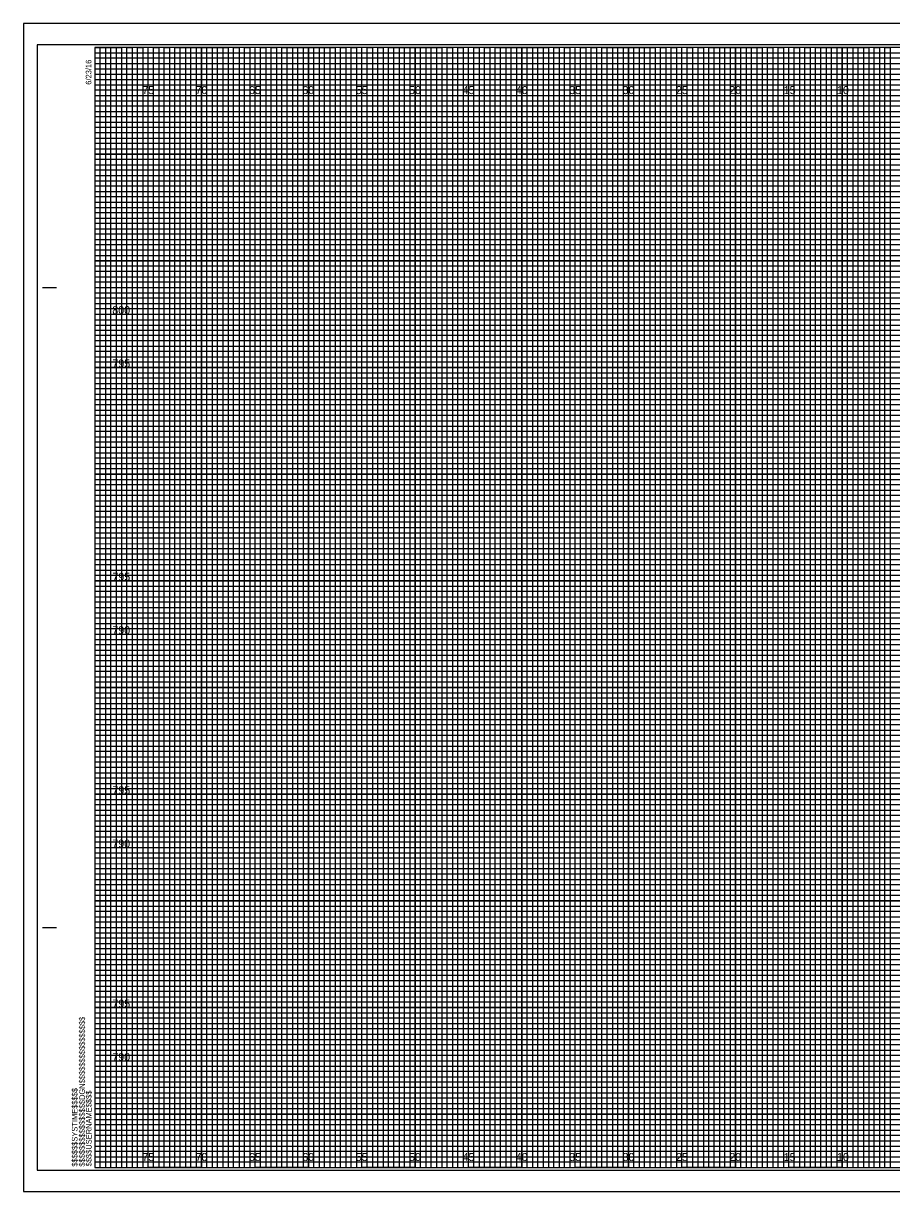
# Model space of a CAD drawing. Extents: x -7 to 162, y -2 to 107.
# Drawn here: x -6.7 to 74.6, y -2.3 to 107.3 of the extents above; entities that cross this region are included whole.
import ezdxf

# ---------------------------------------------------------------- set-up
doc = ezdxf.new("R2010")
doc.units = 0
for name, color, linetype in [('Exist CMT Pavement', 7, 'Continuous'), ('Exist Cross Section Cell', 7, 'Continuous'), ('Exist XS Center Line Elevation Label', 7, 'Continuous'), ('Prop CMT Concrete Structures', 7, 'Continuous'), ('Prop CMT Pvmt Course 1 Wedge', 7, 'Continuous'), ('Prop CMT Pvmt Course 2', 7, 'Continuous'), ('Prop CMT Pvmt Course 2 Wedge', 7, 'Continuous'), ('Prop CMT Pvmt Course 3', 7, 'Continuous'), ('Prop XS Offset Labels', 7, 'Continuous'), ('Scratch_Level_0', 7, 'Continuous'), ('Sheet DOT Grid CELL', 7, 'Continuous')]:
    doc.layers.add(name, color=color, linetype=linetype)

msp = doc.modelspace()

# ---------------------------------------------------------------- linework, layer by layer
at = {"layer": 'Exist Cross Section Cell'}
for p, q in [((5, 105), (0, 105)), ((5, 0), (5, 105)), ((15, 105), (10, 105)), ((10, 105), (10, 0)), ((15, 0), (15, 105)), ((25, 105), (20, 105)), ((20, 105), (20, 0)), ((25, 0), (25, 105)), ((35, 105), (30, 105)), ((30, 105), (30, 0)), ((35, 0), (35, 105)), ((45, 105), (40, 105)), ((40, 105), (40, 0)), ((45, 0), (45, 105)), ((55, 105), (50, 105)), ((50, 105), (50, 0)), ((55, 0), (55, 105)), ((65, 105), (60, 105)), ((60, 105), (60, 0)), ((65, 0), (65, 105)), ((75, 105), (70, 105)), ((70, 105), (70, 0)), ((10, 0), (5, 0)), ((20, 0), (15, 0)), ((30, 0), (25, 0)), ((40, 0), (35, 0)), ((50, 0), (45, 0)), ((60, 0), (55, 0)), ((70, 0), (65, 0))]:
    msp.add_line(p, q, dxfattribs=at)
for points in [[(0, 100), (160, 100), (160, 95), (0, 95)], [(0, 90), (160, 90), (160, 85), (0, 85)], [(0, 80), (160, 80), (160, 75), (0, 75)], [(0, 70), (160, 70), (160, 65), (0, 65)], [(0, 60), (160, 60), (160, 55), (0, 55)], [(0, 50), (160, 50), (160, 45), (0, 45)], [(0, 40), (160, 40), (160, 35), (0, 35)], [(0, 30), (160, 30), (160, 25), (0, 25)], [(0, 20), (160, 20), (160, 15), (0, 15)], [(0, 10), (160, 10), (160, 5), (0, 5)]]:
    msp.add_lwpolyline(points, dxfattribs=at)
at = {"layer": 'Exist XS Center Line Elevation Label'}
for points in [[(0, 105), (2.5, 105), (2.5, 0), (7.5, 0), (7.5, 105), (12.5, 105), (12.5, 0), (17.5, 0), (17.5, 105), (22.5, 105), (22.5, 0), (27.5, 0), (27.5, 105), (32.5, 105), (32.5, 0), (37.5, 0), (37.5, 105), (42.5, 105), (42.5, 0), (47.5, 0), (47.5, 105), (52.5, 105), (52.5, 0), (57.5, 0), (57.5, 105), (62.5, 105), (62.5, 0), (67.5, 0), (67.5, 105), (72.5, 105), (72.5, 0), (77.5, 0)], [(0, 102.5), (137.5, 102.5)], [(0, 92.5), (160, 92.5), (160, 97.5), (0, 97.5)], [(0, 82.5), (160, 82.5), (160, 87.5), (0, 87.5)], [(0, 72.5), (160, 72.5), (160, 77.5), (0, 77.5)], [(0, 62.5), (160, 62.5), (160, 67.5), (0, 67.5)], [(0, 52.5), (160, 52.5), (160, 57.5), (0, 57.5)], [(0, 42.5), (160, 42.5), (160, 47.5), (0, 47.5)], [(0, 32.5), (160, 32.5), (160, 37.5), (0, 37.5)], [(0, 22.5), (160, 22.5), (160, 27.5), (0, 27.5)], [(0, 12.5), (160, 12.5), (160, 17.5), (0, 17.5)], [(0, 2.5), (160, 2.5), (160, 7.5), (0, 7.5)]]:
    msp.add_lwpolyline(points, dxfattribs=at)
at = {"layer": 'Prop CMT Concrete Structures'}
for p, q in [((161.65, 107.25), (-6.7, 107.25)), ((-6.7, 107.25), (-6.7, -2.25)), ((-6.7, -2.25), (161.65, -2.25))]:
    msp.add_line(p, q, dxfattribs=at)
at = {"layer": 'Prop CMT Pvmt Course 1 Wedge'}
msp.add_lwpolyline([(-6.7, -2.25), (161.65, -2.25), (161.65, 107.25), (-6.7, 107.25)], close=True, dxfattribs=at)
at = {"layer": 'Prop CMT Pvmt Course 2'}
for p, q in [((-4.9, 82.5), (-3.65, 82.5)), ((-4.85, 82.5), (-3.6, 82.5)), ((-4.9, 22.5), (-3.65, 22.5)), ((-4.85, 22.5), (-3.6, 22.5)), ((0, 0), (0, 0)), ((0, 0), (0, 0)), ((0, 0), (0, 0)), ((0, 0), (0, 0)), ((0, 0), (0, 0)), ((0, 0), (0, 0)), ((0, 0), (0, 0))]:
    msp.add_line(p, q, dxfattribs=at)
msp.add_lwpolyline([(160, 105), (0, 105), (0, 0), (160, 0)], close=True, dxfattribs=at)
at = {"layer": 'Prop CMT Pvmt Course 2 Wedge'}
msp.add_lwpolyline([(-5.4, -0.25), (161.2, -0.25), (161.2, 105.25), (-5.4, 105.25)], close=True, dxfattribs=at)
at = {"layer": 'Prop CMT Pvmt Course 3'}
for points in [[(0, 0), (0.5, 0), (0.5, 105), (1, 105), (1, 0)], [(1, 0), (1.5, 0), (1.5, 105), (2, 105), (2, 0)], [(2.5, 0), (3, 0), (3, 105), (3.5, 105), (3.5, 0)], [(3.5, 0), (4, 0), (4, 105), (4.5, 105), (4.5, 0)], [(5, 0), (5.5, 0), (5.5, 105), (6, 105), (6, 0)], [(6, 0), (6.5, 0), (6.5, 105), (7, 105), (7, 0)], [(7.5, 0), (8, 0), (8, 105), (8.5, 105), (8.5, 0)], [(8.5, 0), (9, 0), (9, 105), (9.5, 105), (9.5, 0)], [(10, 0), (10.5, 0), (10.5, 105), (11, 105), (11, 0)], [(11, 0), (11.5, 0), (11.5, 105), (12, 105), (12, 0)], [(12.5, 0), (13, 0), (13, 105), (13.5, 105), (13.5, 0)], [(13.5, 0), (14, 0), (14, 105), (14.5, 105), (14.5, 0)], [(15, 0), (15.5, 0), (15.5, 105), (16, 105), (16, 0)], [(16, 0), (16.5, 0), (16.5, 105), (17, 105), (17, 0)], [(17.5, 0), (18, 0), (18, 105), (18.5, 105), (18.5, 0)], [(18.5, 0), (19, 0), (19, 105), (19.5, 105), (19.5, 0)], [(20, 0), (20.5, 0), (20.5, 105), (21, 105), (21, 0)], [(21, 0), (21.5, 0), (21.5, 105), (22, 105), (22, 0)], [(22.5, 0), (23, 0), (23, 105), (23.5, 105), (23.5, 0)], [(23.5, 0), (24, 0), (24, 105), (24.5, 105), (24.5, 0)], [(25, 0), (25.5, 0), (25.5, 105), (26, 105), (26, 0)], [(26, 0), (26.5, 0), (26.5, 105), (27, 105), (27, 0)], [(27.5, 0), (28, 0), (28, 105), (28.5, 105), (28.5, 0)], [(28.5, 0), (29, 0), (29, 105), (29.5, 105), (29.5, 0)], [(30, 0), (30.5, 0), (30.5, 105), (31, 105), (31, 0)], [(31, 0), (31.5, 0), (31.5, 105), (32, 105), (32, 0)], [(32.5, 0), (33, 0), (33, 105), (33.5, 105), (33.5, 0)], [(33.5, 0), (34, 0), (34, 105), (34.5, 105), (34.5, 0)], [(35, 0), (35.5, 0), (35.5, 105), (36, 105), (36, 0)], [(36, 0), (36.5, 0), (36.5, 105), (37, 105), (37, 0)], [(37.5, 0), (38, 0), (38, 105), (38.5, 105), (38.5, 0)], [(38.5, 0), (39, 0), (39, 105), (39.5, 105), (39.5, 0)], [(40, 0), (40.5, 0), (40.5, 105), (41, 105), (41, 0)], [(41, 0), (41.5, 0), (41.5, 105), (42, 105), (42, 0)], [(42.5, 0), (43, 0), (43, 105), (43.5, 105), (43.5, 0)], [(43.5, 0), (44, 0), (44, 105), (44.5, 105), (44.5, 0)], [(45, 0), (45.5, 0), (45.5, 105), (46, 105), (46, 0)], [(46, 0), (46.5, 0), (46.5, 105), (47, 105), (47, 0)], [(47.5, 0), (48, 0), (48, 105), (48.5, 105), (48.5, 0)], [(48.5, 0), (49, 0), (49, 105), (49.5, 105), (49.5, 0)], [(50, 0), (50.5, 0), (50.5, 105), (51, 105), (51, 0)], [(51, 0), (51.5, 0), (51.5, 105), (52, 105), (52, 0)], [(52.5, 0), (53, 0), (53, 105), (53.5, 105), (53.5, 0)], [(53.5, 0), (54, 0), (54, 105), (54.5, 105), (54.5, 0)], [(55, 0), (55.5, 0), (55.5, 105), (56, 105), (56, 0)], [(56, 0), (56.5, 0), (56.5, 105), (57, 105), (57, 0)], [(57.5, 0), (58, 0), (58, 105), (58.5, 105), (58.5, 0)], [(58.5, 0), (59, 0), (59, 105), (59.5, 105), (59.5, 0)], [(60, 0), (60.5, 0), (60.5, 105), (61, 105), (61, 0)], [(61, 0), (61.5, 0), (61.5, 105), (62, 105), (62, 0)], [(62.5, 0), (63, 0), (63, 105), (63.5, 105), (63.5, 0)], [(63.5, 0), (64, 0), (64, 105), (64.5, 105), (64.5, 0)], [(65, 0), (65.5, 0), (65.5, 105), (66, 105), (66, 0)], [(66, 0), (66.5, 0), (66.5, 105), (67, 105), (67, 0)], [(67.5, 0), (68, 0), (68, 105), (68.5, 105), (68.5, 0)], [(68.5, 0), (69, 0), (69, 105), (69.5, 105), (69.5, 0)], [(70, 0), (70.5, 0), (70.5, 105), (71, 105), (71, 0)], [(71, 0), (71.5, 0), (71.5, 105), (72, 105), (72, 0)], [(72.5, 0), (73, 0), (73, 105), (73.5, 105), (73.5, 0)], [(73.5, 0), (74, 0), (74, 105), (74.5, 105), (74.5, 0)]]:
    msp.add_lwpolyline(points, dxfattribs=at)
at = {"layer": 'Scratch_Level_0'}
for p, q in [((0, 104.5), (130, 104.5)), ((130, 103.99), (0, 103.99)), ((0, 103.99), (0, 103.5)), ((0, 103.5), (130, 103.5)), ((130, 102.95), (0, 102.95)), ((0, 102.95), (0, 102)), ((0, 102), (160, 102))]:
    msp.add_line(p, q, dxfattribs=at)
for points in [[(0, 101.5), (135, 101.5), (160, 101.5), (160, 101), (0, 101)], [(0, 100.5), (160, 100.5), (160, 99.5), (0, 99.5)], [(0, 99), (160, 99), (160, 98.5), (0, 98.49)], [(0, 98), (160, 98), (160, 97), (0, 97)], [(0, 96.5), (160, 96.5), (160, 96), (0, 96)], [(0, 95.5), (160, 95.5), (160, 94.5), (0, 94.5)], [(0, 94), (160, 94), (160, 93.5), (0, 93.5)], [(0, 93), (160, 93), (160, 92), (0, 92)], [(0, 91.5), (160, 91.5), (160, 91), (0, 91)], [(0, 90.5), (160, 90.5), (160, 89.5), (0, 89.5)], [(0, 89), (160, 89), (160, 88.5), (0, 88.5)], [(0, 88), (160, 88), (160, 86.98), (160, 86.5), (160, 86), (0, 86)], [(0, 87), (160, 87), (160, 86.5), (0, 86.5)], [(0, 85.5), (160, 85.5), (160, 84.5), (0, 84.52)], [(0, 84.52), (160, 84.5), (160, 84), (0, 84)], [(0, 83.5), (160, 83.5), (160, 83), (0, 83)], [(0, 82), (160, 82), (160, 81.5), (0, 81.5)], [(0, 81), (160, 81), (160, 80.5), (0, 80.5)], [(-0.04, 79.45), (160, 79.45), (160, 78.94), (-0.04, 78.94)], [(0, 78.5), (160, 78.5), (160, 78), (0, 78)], [(0, 77), (160, 77), (160, 76.5), (0, 76.5)], [(0, 76), (160, 76), (160, 75.5), (0, 75.5)], [(0, 74.5), (160, 74.5), (160, 74), (0, 74)], [(0, 73.5), (160, 73.5), (160, 73), (0, 73)], [(0, 72), (160, 72), (160, 71.5), (0, 71.5)], [(0, 71), (160, 71), (160, 70.5), (0, 70.5)], [(0, 69.5), (160, 69.5), (160, 68.99), (0, 69)], [(0, 68.5), (160, 68.5), (160, 68), (0, 68)], [(0, 67), (160, 67), (160, 66.5), (0, 66.5)], [(0, 66), (160, 66), (160, 65.5), (0, 65.5)], [(0, 64.5), (160, 64.5), (160, 64), (0, 64)], [(0, 63.5), (160, 63.5), (160, 63), (0, 63)], [(0, 62), (160, 62), (160, 61.5), (0, 61.5)], [(0, 61), (160, 61), (160, 60.5), (0, 60.5)], [(0, 59.5), (160, 59.5), (160, 59), (0, 59)], [(0, 58.5), (160.03, 58.45), (160, 58), (0, 58)], [(0, 57), (160, 57), (160, 56.5), (0, 56.5)], [(0, 56), (160, 56), (160, 55.5), (0, 55.5)], [(0, 54.5), (160, 54.5), (160, 54), (0, 54)], [(0, 53.5), (160, 53.5), (160, 53), (0, 53)], [(0, 52), (160, 52), (160, 51.5), (0, 51.5)], [(0, 51), (160, 51), (160, 50.5), (0, 50.5)], [(0, 49.5), (160, 49.5), (160, 49), (0, 49)], [(0, 48.5), (160, 48.5), (160, 48), (0, 48)], [(0, 47), (160, 47), (160, 46.5), (0, 46.5)], [(0, 46), (160, 46), (160, 45.5), (0, 45.5)], [(0, 44.5), (160, 44.5), (160, 44), (0, 44)], [(0, 43.5), (160, 43.5), (160, 43), (0, 43)], [(0, 42), (160, 42), (160, 41.5), (0, 41.5)], [(0, 41), (160, 41), (160, 40.5), (0, 40.5)], [(0, 39.5), (160, 39.5), (160, 38.99), (0, 39)], [(0, 38.5), (160, 38.5), (160, 38), (0, 38)], [(0, 37), (160, 37), (160, 36.5), (0, 36.5)], [(0, 36), (160, 36), (160, 35.5), (0, 35.5)], [(0, 34.5), (160, 34.5), (160, 34), (0, 34)], [(0, 33.5), (160, 33.5), (160, 33), (0, 33)], [(0, 32), (160, 32), (160, 31.5), (0, 31.5)], [(0, 31), (160, 31), (160, 30.5), (0, 30.5)], [(0, 29.5), (160, 29.5), (160, 29), (0, 29)], [(0, 28.5), (160.03, 28.46), (160, 28), (0, 28)], [(0, 27), (160, 27), (160, 26.5), (0, 26.5)], [(0, 26), (160, 26), (160, 25.5), (0, 25.5)], [(0, 24.5), (160, 24.5), (160, 24), (0, 24)], [(0, 23.5), (160, 23.5), (160, 23), (0, 23)], [(0, 22), (160, 22), (160, 21.5), (0, 21.5)], [(0, 21), (160, 21), (160, 20.5), (0, 20.5)], [(0, 19.5), (160, 19.5), (160, 19), (0, 19)], [(0, 18.5), (160, 18.5), (160, 18), (0, 18)], [(0, 17), (160, 17), (160, 16.5), (0, 16.5)], [(0, 16), (160, 16), (160, 15.5), (0, 15.5)], [(0, 14.5), (160, 14.5), (160, 14), (0, 14)], [(0, 13.5), (160, 13.5), (160, 13), (0, 13)], [(0, 12), (160, 12), (160, 11.5), (0, 11.5)], [(0, 11), (160, 11), (160, 10.5), (0, 10.5)], [(0, 9.5), (160, 9.5), (160, 9), (0, 9)], [(0, 8.5), (160, 8.5), (160, 8), (0, 8)], [(0, 7), (160, 7), (160, 6.5), (0, 6.5)], [(0, 6), (160, 6), (160, 5.5), (0, 5.5)], [(0, 4.5), (160, 4.5), (160, 4), (0, 4)], [(0, 3.5), (160, 3.5), (160, 3), (0, 3)], [(0, 2), (160, 2), (160, 1.5), (0, 1.5)], [(0, 1), (160, 1), (160, 0.5), (0, 0.5)]]:
    msp.add_lwpolyline(points, dxfattribs=at)
at = {"layer": 'Sheet DOT Grid CELL'}
for p, q in [((5, 0), (5, 105)), ((10, 0), (10, 105)), ((15, 0), (15, 105)), ((20, 0), (20, 105)), ((25, 0), (25, 105)), ((30, 0), (30, 105)), ((35, 0), (35, 105)), ((40, 0), (40, 105)), ((45, 0), (45, 105)), ((50, 0), (50, 105)), ((55, 0), (55, 105)), ((60, 0), (60, 105)), ((65, 0), (65, 105)), ((70, 0), (70, 105)), ((0, 100), (160, 100)), ((0, 95), (160, 95)), ((0, 90), (160, 90)), ((0, 85), (160, 85)), ((0, 80), (160, 80)), ((0, 75), (160, 75)), ((0, 70), (160, 70)), ((0, 65), (160, 65)), ((0, 60), (160, 60)), ((0, 55), (160, 55)), ((0, 50), (160, 50)), ((0, 45), (160, 45)), ((0, 40), (160, 40)), ((0, 35), (160, 35)), ((0, 30), (160, 30)), ((0, 25), (160, 25)), ((0, 20), (160, 20)), ((0, 15), (160, 15)), ((0, 10), (160, 10)), ((0, 5), (160, 5))]:
    msp.add_line(p, q, dxfattribs=at)

# ---------------------------------------------------------------- texts
at = {"layer": 'Exist CMT Pavement'}
for s, p in [('800', (1.63, 80)), ('795', (1.64, 75)), ('795', (1.64, 55)), ('790', (1.63, 50)), ('795', (1.64, 35)), ('790', (1.63, 30)), ('795', (1.64, 15)), ('790', (1.63, 10))]:
    msp.add_text(s, height=0.75, dxfattribs=at).set_placement(p)
at = {"layer": 'Prop CMT Pvmt Course 2'}
for s, p in [('6/23/16', (-0.33, 101.5)), ('$$$$$$$$$$$$$$$$DGN$$$$$$$$$$$$$$$$', (-0.94, 0.09)), ('$$$$$$SYSTIME$$$$$', (-1.63, 0.09)), ('$$$$USERNAME$$$$', (-0.31, 0.12))]:
    msp.add_text(s, height=0.525, rotation=90, dxfattribs=at).set_placement(p)
at = {"layer": 'Prop XS Offset Labels'}
for s, p in [('75', (4.44, 100.62)), ('70', (9.43, 100.62)), ('65', (14.44, 100.62)), ('60', (19.43, 100.62)), ('55', (24.44, 100.62)), ('50', (29.43, 100.62)), ('45', (34.44, 100.62)), ('40', (39.43, 100.62)), ('35', (44.44, 100.62)), ('30', (49.43, 100.62)), ('25', (54.44, 100.62)), ('20', (59.43, 100.62)), ('15', (64.53, 100.62)), ('10', (69.52, 100.62)), ('75', (4.44, 0.62)), ('70', (9.43, 0.62)), ('65', (14.44, 0.62)), ('60', (19.43, 0.62)), ('55', (24.44, 0.62)), ('50', (29.43, 0.62)), ('45', (34.44, 0.62)), ('40', (39.43, 0.62)), ('35', (44.44, 0.62)), ('30', (49.43, 0.62)), ('25', (54.44, 0.62)), ('20', (59.43, 0.62)), ('15', (64.53, 0.62)), ('10', (69.52, 0.62))]:
    msp.add_text(s, height=0.75, dxfattribs=at).set_placement(p)

doc.saveas('drawing.dxf')
